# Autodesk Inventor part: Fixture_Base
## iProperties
Shininess: 64.0
Length Units: 11269
Angle Units: 11279
Time Units: 11290
Mass Units: 11286
Length Display Precision: 3
Angle Display Precision: 2
Compacted: True
Part Number: Fixture_Base
Document SubType Name: Modeling
Created: 2003-06
Designer: Administrator
Manufacturer: Standard
Standards Organization: Custom
Density: 1 g/cm^3
Density: 0.0
Volumn: 0.0
Area: 0.0
PropertySet Name: Model Information
Control State: 0
Master: False
Checked Out: False
Author: Administrator
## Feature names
1. Extrusion1
2. Hole1
3. Hole2
4. Mirror1
